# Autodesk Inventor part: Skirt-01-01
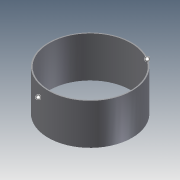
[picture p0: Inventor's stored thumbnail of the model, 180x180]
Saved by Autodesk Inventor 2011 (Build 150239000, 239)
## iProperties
Created: 2010-06
Part Number: Skirt-01-01
Document SubType Name: Modeling
Designer: mklassen
Density: 1 g/cm^3
OD: 36.000 in
THK: 0.500 in
LEN: 1.500 ft
SKVOFS: 6.000 in
Author: mklassen
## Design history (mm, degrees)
sketch "skSkirt"
  geometry: C1 r 469.9 at (0, 0); C2 r 457.2 at (0, 0); 1 further point
  constraints: 2 centre point, 1 coincident
  dimensions: "d0" = 914.4 diameter of C2 (derived); "d1" = 12.7 radial gap between concentric circles of C1 C2 (derived)
extrude "Extrusion1" new body sketch "skSkirt" stored distance "d2" = 457.2 (derived); taper "d3" = 0 deg
body "Solid1"
other parameters: "d4" = 152.4 (derived), "d5" = 0
